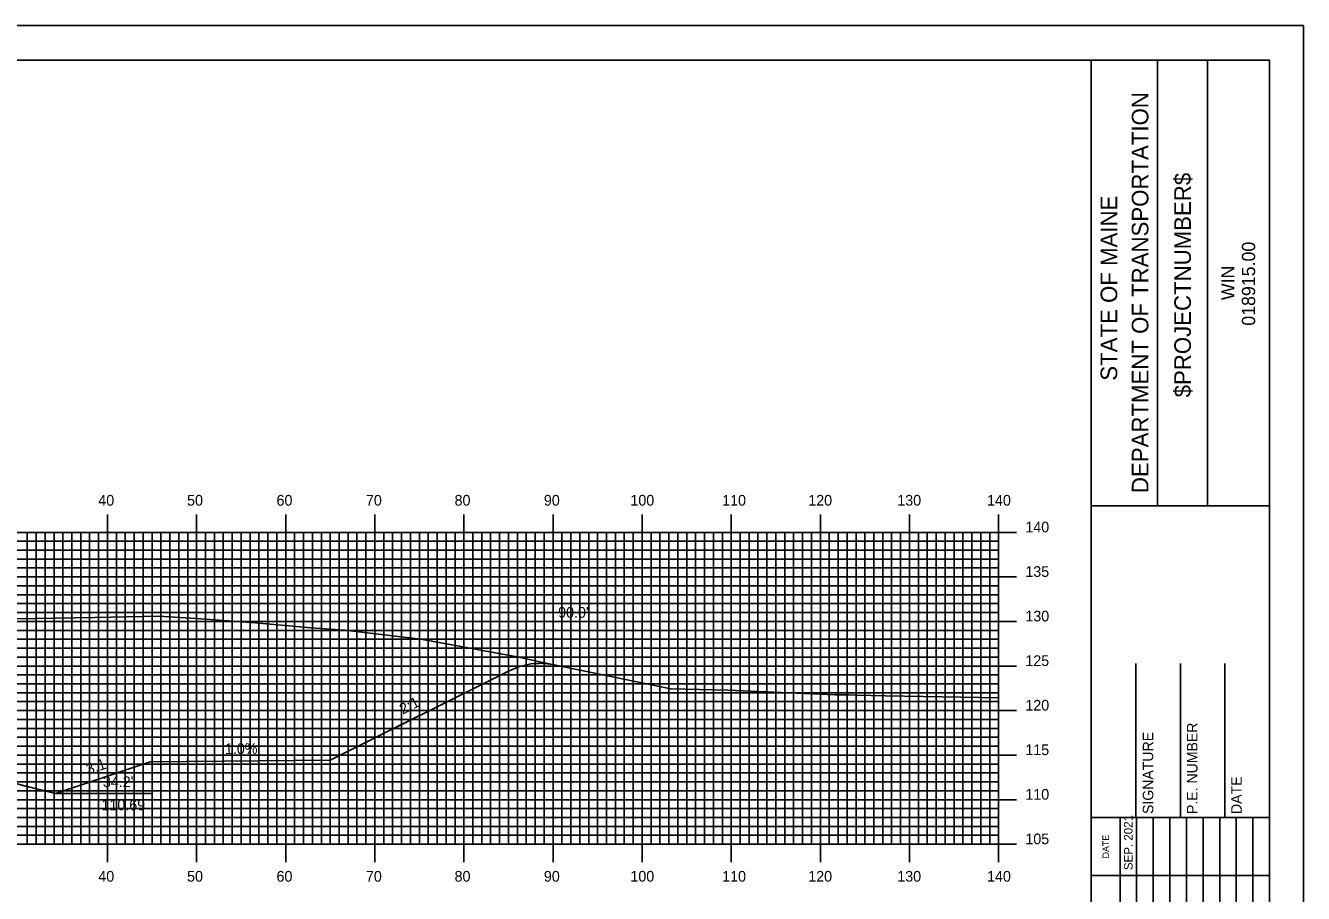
# Model space of a CAD drawing. Extents: x 1767300 to 1767643, y 442591 to 442811.
# Drawn here: x 1767496.7 to 1767640.1, y 442713.1 to 442810.5 of the extents above; entities that cross this region are included whole.
import ezdxf

# ---------------------------------------------------------------- set-up
doc = ezdxf.new("R2010")
doc.units = 0
for name, color, linetype in [('ANNOTATION', 7, 'Continuous'), ('BORDER', 7, 'Continuous'), ('D_Roadway_Centerline', 7, 'Continuous'), ('D_Roadway_SlopeLines', 7, 'Continuous'), ('D_Text_Standard', 7, 'Continuous'), ('H_V ANNOTATION', 7, 'Continuous'), ('MAJOR', 7, 'Continuous'), ('MINOR', 7, 'Continuous'), ('PDRAIN', 7, 'Continuous'), ('PLOT BOUNDARY', 7, 'Continuous'), ('S_Roadway_Centerline', 7, 'Continuous')]:
    doc.layers.add(name, color=color, linetype=linetype)

msp = doc.modelspace()

# ---------------------------------------------------------------- linework, layer by layer
at = {"layer": 'BORDER'}
for p, q in [((1767616.34, 442596.67), (1767616.34, 442806.67)), ((1767623.79, 442756.66), (1767623.79, 442806.66)), ((1767629.38, 442756.66), (1767629.38, 442806.66)), ((1767616.34, 442756.65), (1767636.34, 442756.65)), ((1767621.34, 442721.67), (1767621.34, 442738.97)), ((1767626.34, 442721.67), (1767626.34, 442738.97)), ((1767631.34, 442721.67), (1767631.34, 442738.97)), ((1767616.34, 442721.67), (1767636.34, 442721.67))]:
    msp.add_line(p, q, dxfattribs=at)
msp.add_lwpolyline([(1767316.34, 442596.67), (1767636.34, 442596.67), (1767636.34, 442806.67), (1767316.34, 442806.67)], close=True, dxfattribs=at)
for points in [[(1767619.57, 442715.17), (1767619.57, 442721.67)], [(1767621.43, 442686.68), (1767621.43, 442721.67)], [(1767623.29, 442721.67), (1767623.29, 442686.68)], [(1767625.16, 442686.68), (1767625.16, 442721.67)], [(1767627.02, 442686.68), (1767627.02, 442721.67)], [(1767628.88, 442686.68), (1767628.88, 442721.67)], [(1767630.75, 442686.68), (1767630.75, 442721.67)], [(1767632.61, 442686.68), (1767632.61, 442721.67)], [(1767634.47, 442686.68), (1767634.47, 442721.67)], [(1767619.57, 442686.68), (1767619.57, 442720.26)], [(1767616.34, 442715.17), (1767636.34, 442715.17)]]:
    msp.add_lwpolyline(points, dxfattribs=at)
at = {"layer": 'D_Roadway_Centerline'}
msp.add_lwpolyline([(1767496.11, 442725.35), (1767500.11, 442724.35), (1767500.11, 442724.35), (1767503.46, 442725.47), (1767510.74, 442727.9), (1767510.75, 442727.9), (1767530.92, 442728.1), (1767530.93, 442728.1), (1767544.95, 442735.11), (1767550.93, 442738.1), (1767550.94, 442738.11), (1767552.19, 442738.62), (1767553.44, 442738.91), (1767554.4, 442738.97), (1767554.69, 442738.98), (1767555.24, 442738.91), (1767555.94, 442738.83)], dxfattribs=at)
at = {"layer": 'D_Roadway_SlopeLines'}
for points in [[(1767510.74, 442727.9), (1767530.92, 442728.1), (1767550.94, 442738.11), (1767552.19, 442738.62), (1767553.44, 442738.91), (1767554.69, 442738.98), (1767555.94, 442738.83)], [(1767485.94, 442727.9), (1767500.11, 442724.35)], [(1767500.11, 442724.35), (1767510.74, 442727.9)]]:
    msp.add_lwpolyline(points, dxfattribs=at)
at = {"layer": 'MAJOR'}
for p, q in [((1767505.94, 442755.67), (1767505.94, 442753.67)), ((1767515.94, 442755.67), (1767515.94, 442753.67)), ((1767525.94, 442755.67), (1767525.94, 442753.67)), ((1767535.94, 442755.67), (1767535.94, 442753.67)), ((1767545.94, 442755.67), (1767545.94, 442753.67)), ((1767555.94, 442755.67), (1767555.94, 442753.67)), ((1767565.94, 442755.67), (1767565.94, 442753.67)), ((1767575.94, 442755.67), (1767575.94, 442753.67)), ((1767585.94, 442755.67), (1767585.94, 442753.67)), ((1767595.94, 442755.67), (1767595.94, 442753.67)), ((1767605.94, 442755.67), (1767605.94, 442753.67)), ((1767325.94, 442753.67), (1767605.94, 442753.67)), ((1767325.94, 442753.67), (1767605.94, 442753.67)), ((1767505.94, 442718.67), (1767505.94, 442753.67)), ((1767515.94, 442718.67), (1767515.94, 442753.67)), ((1767525.94, 442718.67), (1767525.94, 442753.67)), ((1767535.94, 442718.67), (1767535.94, 442753.67)), ((1767545.94, 442718.67), (1767545.94, 442753.67)), ((1767555.94, 442718.67), (1767555.94, 442753.67)), ((1767565.94, 442718.67), (1767565.94, 442753.67)), ((1767575.94, 442718.67), (1767575.94, 442753.67)), ((1767585.94, 442718.67), (1767585.94, 442753.67)), ((1767595.94, 442718.67), (1767595.94, 442753.67)), ((1767607.94, 442753.67), (1767603.93, 442753.67)), ((1767605.94, 442718.67), (1767605.94, 442753.67)), ((1767605.94, 442718.67), (1767605.94, 442753.67)), ((1767325.94, 442748.67), (1767605.94, 442748.67)), ((1767607.94, 442748.67), (1767603.93, 442748.67)), ((1767325.94, 442743.67), (1767605.94, 442743.67)), ((1767607.94, 442743.67), (1767603.93, 442743.67)), ((1767325.94, 442738.67), (1767605.94, 442738.67)), ((1767607.94, 442738.67), (1767603.93, 442738.67)), ((1767325.94, 442733.67), (1767605.94, 442733.67)), ((1767607.94, 442733.67), (1767603.93, 442733.67)), ((1767325.94, 442728.67), (1767605.94, 442728.67)), ((1767607.94, 442728.67), (1767603.93, 442728.67)), ((1767325.94, 442723.67), (1767605.94, 442723.67)), ((1767607.94, 442723.67), (1767603.93, 442723.67)), ((1767325.94, 442718.67), (1767605.94, 442718.67)), ((1767325.94, 442718.67), (1767605.94, 442718.67)), ((1767505.94, 442716.66), (1767505.94, 442718.67)), ((1767515.94, 442716.66), (1767515.94, 442718.67)), ((1767525.94, 442716.66), (1767525.94, 442718.67)), ((1767535.94, 442716.66), (1767535.94, 442718.67)), ((1767545.94, 442716.66), (1767545.94, 442718.67)), ((1767555.94, 442716.66), (1767555.94, 442718.67)), ((1767565.94, 442716.66), (1767565.94, 442718.67)), ((1767575.94, 442716.66), (1767575.94, 442718.67)), ((1767585.94, 442716.66), (1767585.94, 442718.67)), ((1767595.94, 442716.66), (1767595.94, 442718.67)), ((1767607.94, 442718.67), (1767603.93, 442718.67)), ((1767605.94, 442716.66), (1767605.94, 442718.67))]:
    msp.add_line(p, q, dxfattribs=at)
at = {"layer": 'MINOR'}
for p, q in [((1767325.94, 442752.67), (1767605.94, 442752.67)), ((1767496.94, 442718.67), (1767496.94, 442753.67)), ((1767497.94, 442718.67), (1767497.94, 442753.67)), ((1767498.94, 442718.67), (1767498.94, 442753.67)), ((1767499.94, 442718.67), (1767499.94, 442753.67)), ((1767500.94, 442718.67), (1767500.94, 442753.67)), ((1767501.94, 442718.67), (1767501.94, 442753.67)), ((1767502.94, 442718.67), (1767502.94, 442753.67)), ((1767503.94, 442718.67), (1767503.94, 442753.67)), ((1767504.94, 442718.67), (1767504.94, 442753.67)), ((1767506.94, 442718.67), (1767506.94, 442753.67)), ((1767507.94, 442718.67), (1767507.94, 442753.67)), ((1767508.94, 442718.67), (1767508.94, 442753.67)), ((1767509.94, 442718.67), (1767509.94, 442753.67)), ((1767510.94, 442718.67), (1767510.94, 442753.67)), ((1767511.94, 442718.67), (1767511.94, 442753.67)), ((1767512.94, 442718.67), (1767512.94, 442753.67)), ((1767513.94, 442718.67), (1767513.94, 442753.67)), ((1767514.94, 442718.67), (1767514.94, 442753.67)), ((1767516.94, 442718.67), (1767516.94, 442753.67)), ((1767517.94, 442718.67), (1767517.94, 442753.67)), ((1767518.94, 442718.67), (1767518.94, 442753.67)), ((1767519.94, 442718.67), (1767519.94, 442753.67)), ((1767520.94, 442718.67), (1767520.94, 442753.67)), ((1767521.94, 442718.67), (1767521.94, 442753.67)), ((1767522.94, 442718.67), (1767522.94, 442753.67)), ((1767523.94, 442718.67), (1767523.94, 442753.67)), ((1767524.94, 442718.67), (1767524.94, 442753.67)), ((1767526.94, 442718.67), (1767526.94, 442753.67)), ((1767527.94, 442718.67), (1767527.94, 442753.67)), ((1767528.94, 442718.67), (1767528.94, 442753.67)), ((1767529.94, 442718.67), (1767529.94, 442753.67)), ((1767530.94, 442718.67), (1767530.94, 442753.67)), ((1767531.94, 442718.67), (1767531.94, 442753.67)), ((1767532.94, 442718.67), (1767532.94, 442753.67)), ((1767533.94, 442718.67), (1767533.94, 442753.67)), ((1767534.94, 442718.67), (1767534.94, 442753.67)), ((1767536.94, 442718.67), (1767536.94, 442753.67)), ((1767537.94, 442718.67), (1767537.94, 442753.67)), ((1767538.94, 442718.67), (1767538.94, 442753.67)), ((1767539.94, 442718.67), (1767539.94, 442753.67)), ((1767540.94, 442718.67), (1767540.94, 442753.67)), ((1767541.94, 442718.67), (1767541.94, 442753.67)), ((1767542.94, 442718.67), (1767542.94, 442753.67)), ((1767543.94, 442718.67), (1767543.94, 442753.67)), ((1767544.94, 442718.67), (1767544.94, 442753.67)), ((1767546.94, 442718.67), (1767546.94, 442753.67)), ((1767547.94, 442718.67), (1767547.94, 442753.67)), ((1767548.94, 442718.67), (1767548.94, 442753.67)), ((1767549.94, 442718.67), (1767549.94, 442753.67)), ((1767550.94, 442718.67), (1767550.94, 442753.67)), ((1767551.94, 442718.67), (1767551.94, 442753.67)), ((1767552.94, 442718.67), (1767552.94, 442753.67)), ((1767553.94, 442718.67), (1767553.94, 442753.67)), ((1767554.94, 442718.67), (1767554.94, 442753.67)), ((1767556.94, 442718.67), (1767556.94, 442753.67)), ((1767557.94, 442718.67), (1767557.94, 442753.67)), ((1767558.94, 442718.67), (1767558.94, 442753.67)), ((1767559.94, 442718.67), (1767559.94, 442753.67)), ((1767560.94, 442718.67), (1767560.94, 442753.67)), ((1767561.94, 442718.67), (1767561.94, 442753.67)), ((1767562.94, 442718.67), (1767562.94, 442753.67)), ((1767563.94, 442718.67), (1767563.94, 442753.67)), ((1767564.94, 442718.67), (1767564.94, 442753.67)), ((1767566.94, 442718.67), (1767566.94, 442753.67)), ((1767567.94, 442718.67), (1767567.94, 442753.67)), ((1767568.94, 442718.67), (1767568.94, 442753.67)), ((1767569.94, 442718.67), (1767569.94, 442753.67)), ((1767570.94, 442718.67), (1767570.94, 442753.67)), ((1767571.94, 442718.67), (1767571.94, 442753.67)), ((1767572.94, 442718.67), (1767572.94, 442753.67)), ((1767573.94, 442718.67), (1767573.94, 442753.67)), ((1767574.94, 442718.67), (1767574.94, 442753.67)), ((1767576.94, 442718.67), (1767576.94, 442753.67)), ((1767577.94, 442718.67), (1767577.94, 442753.67)), ((1767578.94, 442718.67), (1767578.94, 442753.67)), ((1767579.94, 442718.67), (1767579.94, 442753.67)), ((1767580.94, 442718.67), (1767580.94, 442753.67)), ((1767581.94, 442718.67), (1767581.94, 442753.67)), ((1767582.94, 442718.67), (1767582.94, 442753.67)), ((1767583.94, 442718.67), (1767583.94, 442753.67)), ((1767584.94, 442718.67), (1767584.94, 442753.67)), ((1767586.94, 442718.67), (1767586.94, 442753.67)), ((1767587.94, 442718.67), (1767587.94, 442753.67)), ((1767588.94, 442718.67), (1767588.94, 442753.67)), ((1767589.94, 442718.67), (1767589.94, 442753.67)), ((1767590.94, 442718.67), (1767590.94, 442753.67)), ((1767591.94, 442718.67), (1767591.94, 442753.67)), ((1767592.94, 442718.67), (1767592.94, 442753.67)), ((1767593.94, 442718.67), (1767593.94, 442753.67)), ((1767594.94, 442718.67), (1767594.94, 442753.67)), ((1767596.94, 442718.67), (1767596.94, 442753.67)), ((1767597.94, 442718.67), (1767597.94, 442753.67)), ((1767598.94, 442718.67), (1767598.94, 442753.67)), ((1767599.94, 442718.67), (1767599.94, 442753.67)), ((1767600.94, 442718.67), (1767600.94, 442753.67)), ((1767601.94, 442718.67), (1767601.94, 442753.67)), ((1767602.94, 442718.67), (1767602.94, 442753.67)), ((1767605.94, 442752.67), (1767603.93, 442752.67)), ((1767603.94, 442718.67), (1767603.94, 442753.67)), ((1767604.94, 442718.67), (1767604.94, 442753.67)), ((1767325.94, 442751.67), (1767605.94, 442751.67)), ((1767605.94, 442751.67), (1767603.93, 442751.67)), ((1767325.94, 442750.67), (1767605.94, 442750.67)), ((1767605.94, 442750.67), (1767603.93, 442750.67)), ((1767325.94, 442749.67), (1767605.94, 442749.67)), ((1767605.94, 442749.67), (1767603.93, 442749.67)), ((1767325.94, 442747.67), (1767605.94, 442747.67)), ((1767605.94, 442747.67), (1767603.93, 442747.67)), ((1767325.94, 442746.67), (1767605.94, 442746.67)), ((1767325.94, 442745.67), (1767605.94, 442745.67)), ((1767605.94, 442746.67), (1767603.93, 442746.67)), ((1767605.94, 442745.67), (1767603.93, 442745.67)), ((1767325.94, 442744.67), (1767605.94, 442744.67)), ((1767605.94, 442744.67), (1767603.93, 442744.67)), ((1767325.94, 442742.67), (1767605.94, 442742.67)), ((1767605.94, 442742.67), (1767603.93, 442742.67)), ((1767325.94, 442741.67), (1767605.94, 442741.67)), ((1767605.94, 442741.67), (1767603.93, 442741.67)), ((1767325.94, 442740.67), (1767605.94, 442740.67)), ((1767605.94, 442740.67), (1767603.93, 442740.67)), ((1767325.94, 442739.67), (1767605.94, 442739.67)), ((1767605.94, 442739.67), (1767603.93, 442739.67)), ((1767325.94, 442737.67), (1767605.94, 442737.67)), ((1767605.94, 442737.67), (1767603.93, 442737.67)), ((1767325.94, 442736.67), (1767605.94, 442736.67)), ((1767325.94, 442735.67), (1767605.94, 442735.67)), ((1767605.94, 442736.67), (1767603.93, 442736.67)), ((1767605.94, 442735.67), (1767603.93, 442735.67)), ((1767325.94, 442734.67), (1767605.94, 442734.67)), ((1767605.94, 442734.67), (1767603.93, 442734.67)), ((1767325.94, 442732.67), (1767605.94, 442732.67)), ((1767605.94, 442732.67), (1767603.93, 442732.67)), ((1767325.94, 442731.67), (1767605.94, 442731.67)), ((1767605.94, 442731.67), (1767603.93, 442731.67)), ((1767325.94, 442730.67), (1767605.94, 442730.67)), ((1767605.94, 442730.67), (1767603.93, 442730.67)), ((1767325.94, 442729.67), (1767605.94, 442729.67)), ((1767605.94, 442729.67), (1767603.93, 442729.67)), ((1767325.94, 442727.67), (1767605.94, 442727.67)), ((1767605.94, 442727.67), (1767603.93, 442727.67)), ((1767325.94, 442726.67), (1767605.94, 442726.67)), ((1767325.94, 442725.67), (1767605.94, 442725.67)), ((1767605.94, 442726.67), (1767603.93, 442726.67)), ((1767605.94, 442725.67), (1767603.93, 442725.67)), ((1767325.94, 442724.67), (1767605.94, 442724.67)), ((1767605.94, 442724.67), (1767603.93, 442724.67)), ((1767325.94, 442722.67), (1767605.94, 442722.67)), ((1767605.94, 442722.67), (1767603.93, 442722.67)), ((1767325.94, 442721.67), (1767605.94, 442721.67)), ((1767605.94, 442721.67), (1767603.93, 442721.67)), ((1767325.94, 442720.67), (1767605.94, 442720.67)), ((1767325.94, 442719.67), (1767605.94, 442719.67)), ((1767605.94, 442720.67), (1767603.93, 442720.67)), ((1767605.94, 442719.67), (1767603.93, 442719.67))]:
    msp.add_line(p, q, dxfattribs=at)
at = {"layer": 'PDRAIN'}
msp.add_line((1767500.11, 442724.35), (1767510.88, 442724.35), dxfattribs=at)
at = {"layer": 'PLOT BOUNDARY'}
msp.add_lwpolyline([(1767300.15, 442590.55), (1767640.15, 442590.55), (1767640.15, 442810.55), (1767300.15, 442810.55)], close=True, dxfattribs=at)
at = {"layer": 'S_Roadway_Centerline'}
msp.add_lwpolyline([(1767493.37, 442743.92), (1767504.53, 442744.11), (1767511.67, 442744.26), (1767515.89, 442744.01), (1767522.55, 442743.53), (1767528.77, 442742.95), (1767532.58, 442742.68), (1767541.09, 442741.67), (1767551.9, 442739.69), (1767554.8, 442739.06), (1767569.14, 442736.1), (1767575.56, 442735.95), (1767587.56, 442735.45), (1767589.17, 442735.43), (1767590, 442735.38), (1767593.24, 442735.32), (1767605.94, 442735.11)], dxfattribs=at)

# ---------------------------------------------------------------- texts
at = {"layer": 'ANNOTATION'}
for s, rotation, p in [('2:1', 26.5663, (1767539.08, 442733.21)), ('1.0%', 0.5707, (1767519.12, 442728.78)), ('3:1', 18.4378, (1767503.77, 442726.48))]:
    msp.add_text(s, height=1.2, rotation=rotation, dxfattribs=at).set_placement(p)
for s, p in [("34.2'", (1767505.42, 442725.08)), ('110.69', (1767505.26, 442722.48))]:
    msp.add_text(s, height=1.2, dxfattribs=at).set_placement(p)
at = {"layer": 'BORDER'}
for s, height, p in [('DEPARTMENT OF TRANSPORTATION', 1.8635, (1767622.75, 442758.08)), ('$PROJECTNUMBER$', 1.8635, (1767627.52, 442768.82)), ('STATE OF MAINE', 1.8635, (1767619.25, 442770.69)), ('018915.00', 1.491, (1767634.73, 442776.86)), ('WIN', 1.491, (1767632.41, 442779.73)), ('SIGNATURE', 1.181, (1767623.3, 442722.06)), ('P.E. NUMBER', 1.1811, (1767628.26, 442722.06)), ('DATE', 1.181, (1767633.22, 442722.06)), ('SEP. 2021', 0.969, (1767620.98, 442715.76)), ('DATE', 0.743, (1767618.34, 442717.08))]:
    msp.add_text(s, height=height, rotation=90, dxfattribs=at).set_placement(p)
at = {"layer": 'D_Text_Standard'}
msp.add_text("90.0'", height=1.2, dxfattribs=at).set_placement((1767556.51, 442744.09))
at = {"layer": 'H_V ANNOTATION'}
for s, p in [('40', (1767504.91, 442756.67)), ('50', (1767514.87, 442756.67)), ('60', (1767524.91, 442756.67)), ('70', (1767534.94, 442756.67)), ('80', (1767544.89, 442756.67)), ('90', (1767554.91, 442756.67)), ('100', (1767564.62, 442756.67)), ('110', (1767574.92, 442756.67)), ('120', (1767584.58, 442756.67)), ('130', (1767594.57, 442756.67)), ('140', (1767604.64, 442756.67)), ('140', (1767608.94, 442753.67)), ('135', (1767608.94, 442748.67)), ('130', (1767608.94, 442743.67)), ('125', (1767608.94, 442738.67)), ('120', (1767608.94, 442733.67)), ('115', (1767608.94, 442728.67)), ('110', (1767608.94, 442723.67)), ('105', (1767608.94, 442718.67)), ('40', (1767504.91, 442714.47)), ('50', (1767514.87, 442714.47)), ('60', (1767524.91, 442714.47)), ('70', (1767534.94, 442714.47)), ('80', (1767544.89, 442714.47)), ('90', (1767554.91, 442714.47)), ('100', (1767564.62, 442714.47)), ('110', (1767574.92, 442714.47)), ('120', (1767584.58, 442714.47)), ('130', (1767594.57, 442714.47)), ('140', (1767604.64, 442714.47))]:
    msp.add_text(s, height=1.2, dxfattribs=at).set_placement(p)

doc.saveas('drawing.dxf')
